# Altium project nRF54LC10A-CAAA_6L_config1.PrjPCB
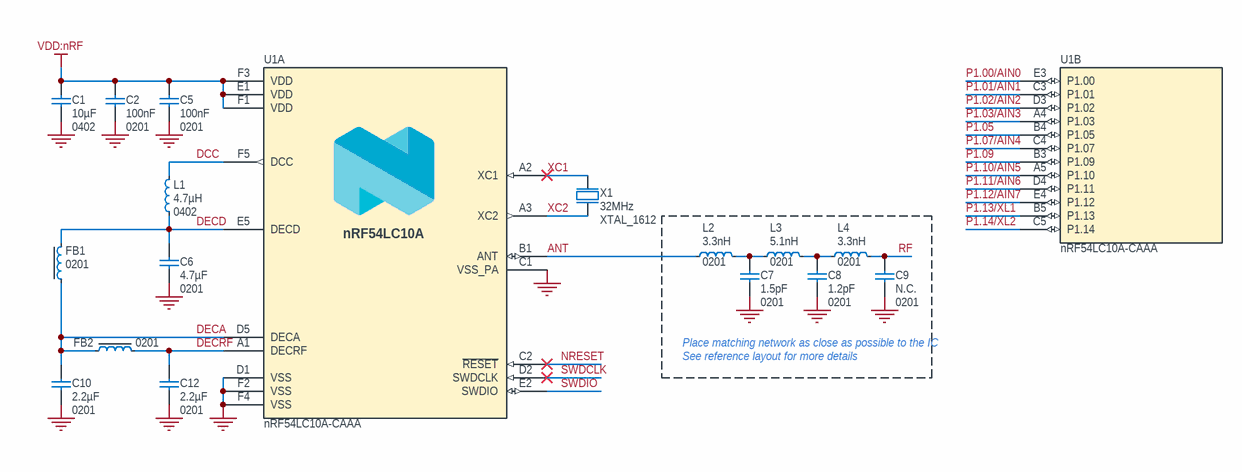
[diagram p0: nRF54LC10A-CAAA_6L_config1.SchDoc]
Revision: 0.2; RefLayoutTitle: Enabled DC/DC - 6 Layer PCB; DrawnBy: Nordic Semiconductor; Device: nRF54LC10A-CAAA; Config: 1; Classification: Public
1 sheet, 17 parts. Net scope: strictly hierarchical (ports join the sheet entries above them; power ports are local).
Board file: nRF54LC10A-CAAA_6L_config1.PcbDoc

## Sheet nRF54LC10A-CAAA_6L_config1.SchDoc
size A4; Organization: Nordic Semiconductor; SheetNumber: 1; SheetTotal: 1; DocumentSize: A4

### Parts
C1  10µF  Footprint Doc: 0402  [CAPC1005X04L]
C2  100nF  Footprint Doc: 0201  [CAPC0603X03L_C]
C5  100nF  Footprint Doc: 0201  [CAPC0603X03L_C]
C6  4.7µF  Footprint Doc: 0201  [CAPC0603X03L_C]
C7  1.5pF  Footprint Doc: 0201  [CAPC0603X03L_C]
C8  1.2pF  Footprint Doc: 0201  [CAPC0603X03L_C]
C9  N.C.  Footprint Doc: 0201  [CAPC0603X03L_C_NC]
C10  2.2µF  Footprint Doc: 0201  [CAPC0603X03L_C]
C12  2.2µF  Footprint Doc: 0201  [CAPC0603X03L_C]
FB1  Footprint Doc: 0201  [INDC0603X03L_C]  (hidden comment: 120R/0.2A)
FB2  Footprint Doc: 0201  [INDC0603X03L_C]  (hidden comment: 120R/0.2A)
L1  4.7µH  Footprint Doc: 0402  [INDDFN10X06X08L31X32L]
L2  3.3nH  Footprint Doc: 0201  [INDC0603X03L_C]
L3  5.1nH  Footprint Doc: 0201  [INDC0603X03L_C]
L4  3.3nH  Footprint Doc: 0201  [INDC0603X03L_C]
U1  nRF54LC10A-CAAA  [BGA29CP35_5X6_239X201X45B20]  (parts A,B of 2)
X1  32MHz  Footprint Doc: XTAL_1612  [BT-XTAL_1612]

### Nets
GND: C1.1 C2.2 C5.2 C6.1 C7.2 C8.2 C9.1 C10.1 C12.1 U1.C1(VSS_PA) U1.D1(VSS) U1.F2(VSS) U1.F4(VSS) X1.2(GND) X1.4(GND)
VDD:nRF: C1.2 C2.1 C5.1 U1.E1(VDD) U1.F1(VDD) U1.F3(VDD)
ANT: L2.1 U1.B1(ANT)
DCC: L1.1 U1.F5(DCC)
DECA: C10.2 FB1.2 FB2.2 U1.D5(DECA)
DECD: C6.2 FB1.1 L1.2 U1.E5(DECD)
DECRF: C12.2 FB2.1 U1.A1(DECRF)
NRESET: U1.C2(~{RESET})
P1.00/AIN0: U1.E3(P1.00)
P1.01/AIN1: U1.C3(P1.01)
P1.02/AIN2: U1.D3(P1.02)
P1.03/AIN3: U1.A4(P1.03)
P1.05: U1.B4(P1.05)
P1.07/AIN4: U1.C4(P1.07)
P1.09: U1.B3(P1.09)
P1.10/AIN5: U1.A5(P1.10)
P1.11/AIN6: U1.D4(P1.11)
P1.12/AIN7: U1.E4(P1.12)
P1.13/XL1: U1.B5(P1.13)
P1.14/XL2: U1.C5(P1.14)
RF: C9.2 L4.2
SWDCLK: U1.D2(SWDCLK)
SWDIO: U1.E2(SWDIO)
XC1: U1.A2(XC1) X1.1(inp)
XC2: U1.A3(XC2) X1.3(out)
NetC7_1: C7.1 L2.2 L3.1
NetC8_1: C8.1 L3.2 L4.1

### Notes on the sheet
- See reference layout for more details
- Place matching network as close as possible to the IC

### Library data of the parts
C1 = C0402-10µF-6.3V-X6S: Capacitor, X6S, ±20%, 6.3V; Manufacturer: N.A.; Part number NEMS: 100200478; Component Status: Active; Pad Count: 2
C2 C5 = C0201-100n-10V-X7R: Capacitor, X7R, ±10%, 10V; Manufacturer: N.A.; Part number NEMS: 100200469; Pad Count: 2; Component Status: Active
C6 = C0201-4.7µ-6V3-X5R-GRM035R60J475ME15J: Capacitor, Ceramic, X5R, ±20%, 6.3V; Manufacturer: Murata; Part number NEMS: 100200685; Component Status: Active; Pad Count: 2; Note: -55°C ~ 85°C; Artikkelnr Noca: N.A.
C7 = C0201-1.5p_RF: RF Chip Cap 0201; Manufacturer: N.A.; Part number NEMS: 100200087; Component Status: Active; Pad Count: 2; Note: High frequency chip capasitors ±5%, NP0
C8 = C0201-1.2p-HQ-Murata: Capacitor, NP0, ±0.05pF, 50V; Manufacturer: Murata; Manufacturer Part Number: GJM0335C1H1R2WB01D; Part number NEMS: 100200457; Component Status: Active; Pad Count: 2; Artikkelnr Noca: N.A.
C9 = C0201-N.C.: Not mounted; Manufacturer: N.A.; Part number NEMS: 100200001; Component Status: Active; Pad Count: 2; Note: Chip Cap; Assembly: Not mounted
C10 C12 = C0201-2µ2-2.5V-X6T-GRM033D80E225ME47D: Capacitor, Ceramic, 2.2µF 2.5V X6T 0201,±20%; Manufacturer: Murata; Part number NEMS: 100200527; Component Status: Active; Pad Count: 2; Note: 2.5V, 20%, X6T; Artikkelnr Noca: N.A.
FB1 FB2 = FB0201-120R@100M-200mA-BLM03AG121SN1D: Ferrite Bead, 120 Ohm @ 100MHz, 200mA, 500 mOhm Max; Manufacturer: Murata; Part number NEMS: 100300419; Component Status: Active; Pad Count: 2; Artikkelnr Noca: N.A.
L1 = L0402-4µ7-PLEA67BCA4R7M-1PT00: Inductor, 300mA, ±20%, 1.08R; Manufacturer: TDK Corporation; Part number NEMS: 100300441; Component Status: Active; Pad Count: 2; Note: Power Inductor ±20%; Artikkelnr Noca: N.A.
L2 L4 = L0201-3n3-HQ-Murata: Inductor, 500mA, ±0.1ｎH, 170mOhm; Manufacturer: Murata; Manufacturer Part Number: LQP03HQ3N3B02; Part number NEMS: 100300220; Component Status: Active; Pad Count: 2; Note: -55°C ~ 125°C; Artikkelnr Noca: N.A.
L3 = L0201-5n1-HQ-Murata: Inductor, 400mA, ±3%, 250mOhm; Manufacturer: Murata; Manufacturer Part Number: LQP03HQ5N1H02; Part number NEMS: 100300235; Component Status: Active; Pad Count: 2; Note: -55°C ~ 125°C; Artikkelnr Noca: N.A.
U1 = nRF54LC10A-CAAA: Multi-protocol Bluetooth Low Energy, IEEE 802.15.4 and 2.4GHz proprietary Wireless MCU; Manufacturer: Nordic Semiconductor; Part number NEMS: 102000467; Component Status: Active; Pad Count: 29; Note: N.A.
X1 = XTAL_SMD1612_32MHz_8pF_Kyocera: XTAL SMD 1612, 32MHz, Cl=8pF, Tot: ±40ppm, Aging: ±1ppm/year; Manufacturer Part Number: CX1612DB32000D0WZRC3; Part number NEMS: 101600029; Component Status: Active; Pad Count: 4; Note: XTAL SMD 32.000MHz; Artikkelnr Noca: N.A.

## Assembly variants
Default: not fitted C9 C11 C12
